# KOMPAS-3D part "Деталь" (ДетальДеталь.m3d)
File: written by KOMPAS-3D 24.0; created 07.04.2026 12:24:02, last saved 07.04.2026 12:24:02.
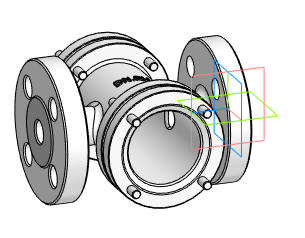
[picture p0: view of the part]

Document properties: Автор: Main; Полное имя файла: D:\DN.ru Аутсерс\Стекло смотровое DN.ru\Исходники\Стекло смотровое DN.ru SG2-34G-F тип В ГОСТ 21836-2021 Ду15 Ру40, углеродистая сталь, фланцевое\ДетальДеталь.m3d

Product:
- Body: Твердое тело1  | qty 1
- Part/product: Деталь
    additional columns: Типовые

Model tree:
1. Твердое тело1  (labels: Твердое тело1)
